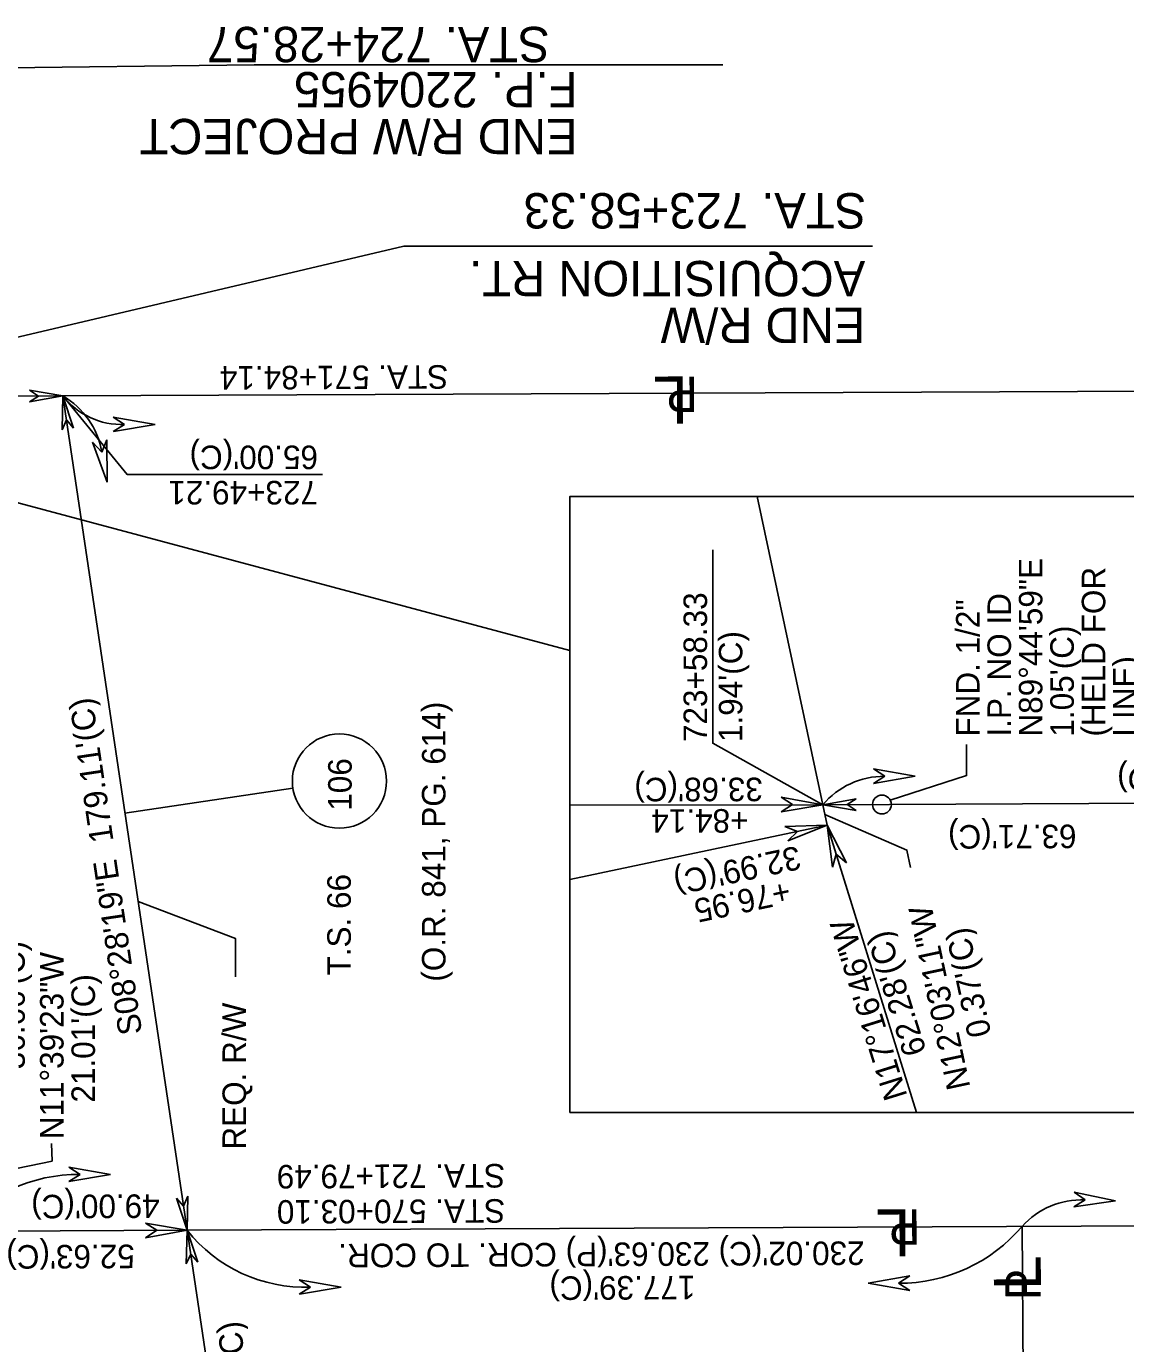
# Model space of a CAD drawing. Extents: x 2003883 to 2008298, y 399149 to 424047.
# Drawn here: x 2005813.6 to 2006047.1, y 404338 to 404617.7 of the extents above; entities that cross this region are included whole.
import ezdxf

# ---------------------------------------------------------------- set-up
doc = ezdxf.new("R2010")
doc.units = 0
for name, color, linetype in [('BaselineFlagRT', 7, 'Continuous'), ('BaselineTextWt0', 7, 'Continuous'), ('BaselineTextWt1', 7, 'Continuous'), ('DetailBorder', 7, 'Continuous'), ('MonRodOpen', 7, 'Continuous'), ('MonText', 7, 'Continuous'), ('ParcelBubble100', 7, 'Continuous'), ('PropertyLine_ep', 7, 'Continuous'), ('PropertyLineStaTie_ep', 7, 'Continuous'), ('PropertyLineSymbol_ep', 7, 'Continuous'), ('PropertyLineText_ep', 7, 'Continuous'), ('RWandLA_Text', 7, 'Continuous'), ('RWandLA_Text_ep', 7, 'Continuous'), ('RWLine', 7, 'Continuous'), ('RWLine_ep', 7, 'Continuous'), ('SubDivLine', 7, 'Continuous'), ('SubDivLineText', 7, 'Continuous')]:
    doc.layers.add(name, color=color, linetype=linetype)

msp = doc.modelspace()

# ---------------------------------------------------------------- linework, layer by layer
at = {"layer": 'BaselineFlagRT'}
for points in [[(2005745.4, 404608.13), (2005862, 404609.5), (2005961.57, 404609.5)], [(2005757.67, 404538.94), (2005893.82, 404571.03), (2005993.39, 404571.03)]]:
    msp.add_lwpolyline(points, dxfattribs=at)
at = {"layer": 'DetailBorder'}
msp.add_line((2005789.04, 404522.6), (2005929.06, 404485.17), dxfattribs=at)
msp.add_lwpolyline([(2005929.06, 404387.08), (2005929.06, 404517.83), (2006112.48, 404517.83), (2006112.48, 404387.08)], close=True, dxfattribs=at)
at = {"layer": 'MonRodOpen'}
msp.add_circle((2005995.37, 404452.45), 2, dxfattribs=at)
at = {"layer": 'MonText'}
msp.add_lwpolyline([(2006013.36, 404465.17), (2006013.36, 404458.6), (2005997.15, 404453.35)], dxfattribs=at)
at = {"layer": 'ParcelBubble100'}
msp.add_circle((2005880.13, 404457.43), 10, dxfattribs=at)
at = {"layer": 'PropertyLine_ep'}
for p, q in [((2005821.38, 404539.22), (2006525.11, 404542.29)), ((2005983.72, 404448.08), (2005982.8, 404452.4)), ((2006025.85, 404262.81), (2006025.15, 404362.88))]:
    msp.add_line(p, q, dxfattribs=at)
at = {"layer": 'PropertyLineStaTie_ep'}
for p, q in [((2005929.06, 404452.32), (2005982.8, 404452.4)), ((2005929.06, 404436.53), (2005983.72, 404448.08))]:
    msp.add_line(p, q, dxfattribs=at)
at = {"layer": 'PropertyLineText_ep'}
for p, q in [((2005840.98, 404533.17), (2005832.08, 404534.72)), ((2005832.08, 404534.72), (2005834.48, 404533.17)), ((2005834.48, 404533.17), (2005832.08, 404531.67)), ((2005832.11, 404531.68), (2005841.01, 404533.18)), ((2005993.6, 404460), (2006002.45, 404458.45)), ((2005996, 404458.45), (2005993.6, 404460)), ((2006002.45, 404458.45), (2005993.6, 404456.9)), ((2005993.6, 404456.9), (2005996, 404458.45)), ((2005822.65, 404375.47), (2005831.5, 404373.92)), ((2005825.05, 404373.92), (2005822.65, 404375.47)), ((2005831.5, 404373.92), (2005822.65, 404372.37)), ((2005822.65, 404372.37), (2005825.05, 404373.92))]:
    msp.add_line(p, q, dxfattribs=at)
for centre, radius, start, end in [((2005833.84, 404549.02), 15.86, 218.1943, 272.3877), ((2005995.82, 404441.38), 17.06, 89.6546, 139.7635), ((2005824.81, 404339.81), 34.11, 89.6546, 139.7635)]:
    msp.add_arc(centre, radius, start, end, dxfattribs=at)
at = {"layer": 'RWandLA_Text'}
for p, q in [((2005816.22, 404539.19), (2005814.3, 404540.43)), ((2005814.3, 404540.43), (2005821.38, 404539.22)), ((2005821.38, 404539.22), (2005814.31, 404537.95)), ((2005814.31, 404537.95), (2005816.22, 404539.19)), ((2005821.2, 404532.03), (2005821.38, 404539.22)), ((2005821.38, 404539.22), (2005823.65, 404532.4)), ((2005822.14, 404534.11), (2005821.2, 404532.03)), ((2005823.65, 404532.4), (2005822.14, 404534.11)), ((2005829.64, 404527.28), (2005830.75, 404529.91)), ((2005830.75, 404529.91), (2005830.77, 404520.93)), ((2005830.77, 404520.93), (2005827.7, 404529.37)), ((2005827.7, 404529.37), (2005829.64, 404527.28)), ((2005870.24, 404455.95), (2005834.57, 404450.64)), ((2005982.8, 404452.4), (2005989.88, 404453.67)), ((2005989.89, 404451.19), (2005982.8, 404452.4)), ((2005989.88, 404453.67), (2005987.96, 404452.42)), ((2005987.96, 404452.42), (2005989.89, 404451.19)), ((2005847.77, 404362.07), (2005845.5, 404368.89)), ((2005845.5, 404368.89), (2005847.01, 404367.17)), ((2005847.01, 404367.17), (2005847.95, 404369.25)), ((2005847.95, 404369.25), (2005847.77, 404362.07)), ((2005847.58, 404354.88), (2005847.77, 404362.07)), ((2005847.77, 404362.07), (2005850.04, 404355.25)), ((2005848.53, 404356.96), (2005847.58, 404354.88)), ((2005850.04, 404355.25), (2005848.53, 404356.96))]:
    msp.add_line(p, q, dxfattribs=at)
for points in [[(2005876.55, 404522.56), (2005835.01, 404522.56), (2005821.38, 404539.22)], [(2005959.42, 404506.5), (2005959.42, 404465.46), (2005982.8, 404452.4)], [(2005858.06, 404415.87), (2005858.06, 404424), (2005837.37, 404431.87)]]:
    msp.add_lwpolyline(points, dxfattribs=at)
msp.add_arc((2005812.81, 404524.47), 17.06, 9.7132, 59.8221, dxfattribs=at)
at = {"layer": 'RWandLA_Text_ep'}
for p, q in [((2005973.95, 404450.88), (2005976.35, 404452.42)), ((2005982.8, 404452.4), (2005973.95, 404450.88)), ((2005973.96, 404453.98), (2005982.8, 404452.4)), ((2005976.35, 404452.42), (2005973.96, 404453.98)), ((2005974.74, 404447.77), (2005983.72, 404448.08)), ((2005977.41, 404446.75), (2005974.74, 404447.77)), ((2005983.72, 404448.08), (2005975.38, 404444.74)), ((2005975.38, 404444.74), (2005977.41, 404446.75)), ((2005984.87, 404439.17), (2005983.72, 404448.08)), ((2005983.72, 404448.08), (2005987.83, 404440.09)), ((2005985.64, 404441.93), (2005984.87, 404439.17)), ((2005987.83, 404440.09), (2005985.64, 404441.93))]:
    msp.add_line(p, q, dxfattribs=at)
for points in [[(2006001.45, 404439.08), (2006000.66, 404442.78), (2005983.25, 404450.3)], [(2005818.94, 404380.5), (2005819.08, 404376.72), (2005796.64, 404372.13)]]:
    msp.add_lwpolyline(points, dxfattribs=at)
at = {"layer": 'RWLine'}
for p, q in [((2005821.38, 404539.22), (2005757.67, 404538.94)), ((2005847.77, 404362.07), (2005821.38, 404539.22)), ((2006112.48, 404452.96), (2005982.8, 404452.4)), ((2005862.67, 404262.03), (2005847.77, 404362.07))]:
    msp.add_line(p, q, dxfattribs=at)
at = {"layer": 'RWLine_ep'}
for p, q in [((2005983.72, 404448.08), (2005968.83, 404517.83)), ((2006002.7, 404387.08), (2005983.72, 404448.08))]:
    msp.add_line(p, q, dxfattribs=at)
at = {"layer": 'SubDivLine'}
for p, q in [((2006525.15, 404365.17), (2005847.77, 404362.07)), ((2005847.77, 404362.07), (2005798.76, 404361.84)), ((2006025.15, 404362.88), (2006025.85, 404262.81))]:
    msp.add_line(p, q, dxfattribs=at)
at = {"layer": 'SubDivLineText'}
for p, q in [((2006036.1, 404367.02), (2006038.55, 404368.49)), ((2006044.99, 404368.27), (2006036.1, 404367.02)), ((2006036.2, 404370.12), (2006044.99, 404368.27)), ((2006038.55, 404368.49), (2006036.2, 404370.12)), ((2005841.32, 404362.04), (2005838.91, 404363.57)), ((2005838.91, 404363.57), (2005847.77, 404362.07)), ((2005847.77, 404362.07), (2005838.93, 404360.47)), ((2005838.93, 404360.47), (2005841.32, 404362.04)), ((2005880.51, 404349.98), (2005871.61, 404351.53)), ((2005871.61, 404351.53), (2005874.01, 404349.98)), ((2005992.42, 404350.8), (2006001.27, 404352.35)), ((2006001.27, 404349.25), (2005992.42, 404350.8)), ((2006001.27, 404352.35), (2005998.87, 404350.8)), ((2005998.87, 404350.8), (2006001.27, 404349.25)), ((2005874.01, 404349.98), (2005871.61, 404348.48)), ((2005871.63, 404348.49), (2005880.53, 404349.99))]:
    msp.add_line(p, q, dxfattribs=at)
for centre, radius, start, end in [((2006037.8, 404351.43), 17.06, 87.7511, 137.86), ((2005872.69, 404381.68), 31.72, 218.1943, 272.3877), ((2005999.11, 404384.91), 34.11, 269.6546, 319.7635)]:
    msp.add_arc(centre, radius, start, end, dxfattribs=at)

# ---------------------------------------------------------------- texts
at = {"layer": 'BaselineTextWt0'}
for s, p in [('STA. 721+79.49', (2005915.32, 404376.13)), ('STA. 570+03.10', (2005915.34, 404368.66))]:
    msp.add_text(s, height=5, rotation=180.2628, dxfattribs=at).set_placement(p)
at = {"layer": 'BaselineTextWt1'}
for s, p in [('STA. 724+28.57', (2005924.79, 404617.59)), ('F.P. 2204955', (2005930.7, 404608)), ('END R/W PROJECT', (2005930.7, 404598.05)), ('STA. 723+58.33', (2005992.02, 404582.28)), ('ACQUISITION RT.', (2005991.82, 404567.88)), ('END R/W', (2005991.82, 404557.93))]:
    msp.add_text(s, height=7.5, rotation=180, dxfattribs=at).set_placement(p)
at = {"layer": 'MonText'}
for s, p in [('N89°44\'59"E', (2006029.45, 404466.88)), ('(HELD FOR', (2006042.81, 404466.88)), ('I.P. NO ID', (2006022.78, 404466.88)), ('FND. 1/2"', (2006016.1, 404466.88)), ("1.05'(C)", (2006036.13, 404466.88)), ('LINE)', (2006049.48, 404466.88))]:
    msp.add_text(s, height=5, rotation=90, dxfattribs=at).set_placement(p)
at = {"layer": 'ParcelBubble100'}
msp.add_text('106', height=5, rotation=90, dxfattribs=at).set_placement((2005882.73, 404451.13))
at = {"layer": 'PropertyLineSymbol_ep'}
for s, height, rotation, p in [('L', 10, 180.2494, (2005954.14, 404543.36)), ('P', 7.5, 180.2494, (2005956.24, 404543.32)), ('L', 10, 180.2628, (2006001.42, 404366.51)), ('P', 7.5, 180.2628, (2006003.52, 404366.47)), ('L', 10, 90.3992, (2006029.15, 404349.31)), ('P', 7.5, 90.3992, (2006029.12, 404347.21))]:
    msp.add_text(s, height=height, rotation=rotation, dxfattribs=at).set_placement(p)
at = {"layer": 'PropertyLineText_ep'}
for s, rotation, p in [('STA. 571+84.14', 180.2504, (2005903.24, 404545.76)), ('(O.R. 841, PG. 614)', 90, (2005902.66, 404414.83)), ("767.44'(C) 767.89'(D)", 180.2504, (2006109.2, 404460.58)), ("33.68'(C)", 180.0758, (2005970.06, 404458.16)), ('+84.14', 180.0758, (2005967.01, 404451.48))]:
    msp.add_text(s, height=5, rotation=rotation, dxfattribs=at).set_placement(p)
at = {"layer": 'RWandLA_Text'}
for s, rotation, p in [("65.00'(C)", 180, (2005875.58, 404528.67)), ('723+49.21', 180, (2005875.58, 404521.17)), ('723+58.33', 90, (2005958.22, 404465.71)), ("1.94'(C)", 90, (2005965.72, 404465.71)), ('S08°28\'19"E  179.11\'(C)', 98.4719, (2005838.25, 404403.91)), ("63.71'(C)", 180.2494, (2006036.69, 404448.19)), ('T.S. 66', 90, (2005882.55, 404416.15)), ('REQ. R/W', 90, (2005860.29, 404379.17)), ("381.39'(C)", 98.4719, (2005863.5, 404312.3))]:
    msp.add_text(s, height=5, rotation=rotation, dxfattribs=at).set_placement(p)
at = {"layer": 'RWandLA_Text_ep'}
for s, rotation, p in [("32.99'(C)", 191.9389, (2005977.5, 404443.73)), ('+76.95', 191.9389, (2005975.33, 404436.49)), ('N12°03\'11"W', 102.0531, (2006014.17, 404392.46)), ('N17°16\'46"W', 107.2795, (2006000.82, 404390.58)), ("62.28'(C)", 107.2795, (2006004.89, 404399.98)), ("0.37'(C)", 102.0531, (2006018.62, 404403.62)), ("36.66'(C)", 90, (2005813.29, 404396.22)), ('N11°39\'23"W', 90, (2005821.53, 404381.37)), ("21.01'(C)", 90, (2005828.21, 404389.15)), ("49.00'(C)", 180.2628, (2005841.94, 404369.68))]:
    msp.add_text(s, height=5, rotation=rotation, dxfattribs=at).set_placement(p)
at = {"layer": 'SubDivLineText'}
for s, rotation, p in [("52.63'(C)", 180.2628, (2005836.64, 404359)), ("230.02'(C) 230.63'(P) COR. TO COR.", 180.2771, (2005991.67, 404359.69)), ("177.39'(C)", 180.2771, (2005955.73, 404352.39))]:
    msp.add_text(s, height=5, rotation=rotation, dxfattribs=at).set_placement(p)

doc.saveas('drawing.dxf')
